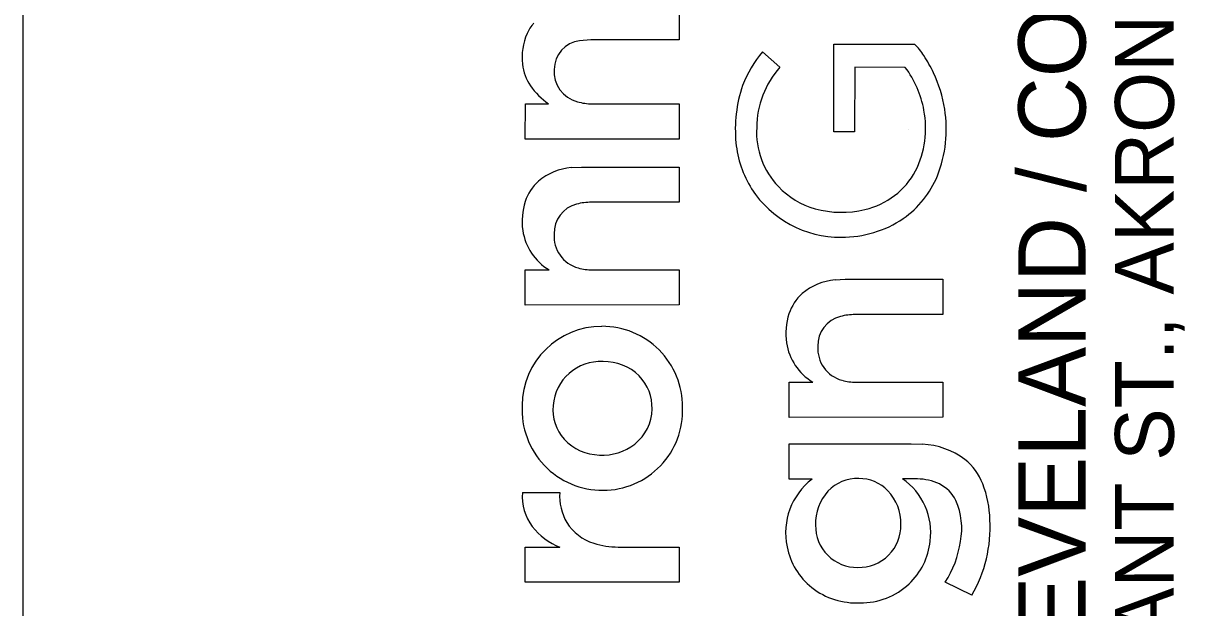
# Model space of a CAD drawing. Extents: x -1.9 to 34, y -1.1 to 22.
# Drawn here: x 32 to 32.984, y 3.094 to 3.59 of the extents above; entities that cross this region are included whole.
import ezdxf

# ---------------------------------------------------------------- set-up
doc = ezdxf.new("R2010")
doc.units = 0
doc.layers.add('SH_Border', color=7, linetype='Continuous')
doc.layers.add('SH_Data', color=7, linetype='Continuous')

msp = doc.modelspace()

# ---------------------------------------------------------------- linework, layer by layer
at = {"layer": 'SH_Border'}
msp.add_line((32, 0.5), (32, 21.5), dxfattribs=at)
at = {"layer": 'SH_Data'}
for p, q in [((32.55571, 3.60548), (32.55571, 3.57568)), ((32.4809, 3.57567), (32.47143, 3.57474)), ((32.55571, 3.57568), (32.4809, 3.57567)), ((32.62636, 3.56548), (32.64114, 3.55241)), ((32.6868, 3.57185), (32.75516, 3.57192)), ((32.6868, 3.49778), (32.6868, 3.57185)), ((32.70448, 3.55241), (32.70432, 3.49775)), ((32.74737, 3.55227), (32.70448, 3.55241)), ((32.42542, 3.49152), (32.42545, 3.52138)), ((32.42545, 3.52138), (32.44515, 3.52138)), ((32.48206, 3.52138), (32.55571, 3.52136)), ((32.55571, 3.52136), (32.55571, 3.49156)), ((32.70432, 3.49775), (32.6868, 3.49778)), ((32.75, 3.5), (32.75, 3.5)), ((32.55571, 3.49156), (32.42542, 3.49152)), ((32.46439, 3.46736), (32.47289, 3.46783)), ((32.47289, 3.46783), (32.55571, 3.46783)), ((32.55571, 3.46783), (32.55571, 3.43804)), ((32.55571, 3.43804), (32.4814, 3.43796)), ((32.42542, 3.38066), (32.44552, 3.38071)), ((32.42542, 3.35086), (32.42542, 3.38066)), ((32.48222, 3.38071), (32.55569, 3.38071)), ((32.55569, 3.38071), (32.55571, 3.35096)), ((32.68784, 3.3722), (32.69634, 3.37266)), ((32.69634, 3.37266), (32.77916, 3.37266)), ((32.77916, 3.37266), (32.77917, 3.34287)), ((32.55571, 3.35096), (32.42542, 3.35086)), ((32.77917, 3.34287), (32.70485, 3.3428)), ((32.64888, 3.2855), (32.66897, 3.28555)), ((32.64888, 3.25569), (32.64888, 3.2855)), ((32.70568, 3.28555), (32.77915, 3.28555)), ((32.77915, 3.28555), (32.77917, 3.25579)), ((32.77917, 3.25579), (32.64888, 3.25569)), ((32.6489, 3.20336), (32.64889, 3.23322)), ((32.64889, 3.23322), (32.75236, 3.23322)), ((32.75236, 3.23322), (32.76191, 3.23285)), ((32.66836, 3.20336), (32.6489, 3.20336)), ((32.75763, 3.20356), (32.74487, 3.20361)), ((32.42299, 3.19193), (32.45454, 3.19193)), ((32.42542, 3.14577), (32.45473, 3.14579)), ((32.42542, 3.11593), (32.42542, 3.14577)), ((32.50413, 3.14581), (32.55571, 3.14573)), ((32.55571, 3.14573), (32.55565, 3.11593)), ((32.55565, 3.11593), (32.42542, 3.11593)), ((32.8036, 3.10491), (32.7812, 3.11598))]:
    msp.add_line(p, q, dxfattribs=at)
for points in [[(32.48218, 3.60553), (32.55571, 3.60548), (32.55571, 3.57568), (32.4809, 3.57567), (32.47143, 3.57474)], [(32.62636, 3.56548), (32.64114, 3.55241)], [(32.74737, 3.55227), (32.70448, 3.55241), (32.70432, 3.49775), (32.6868, 3.49778), (32.6868, 3.57185), (32.75516, 3.57192)], [(32.42542, 3.49152), (32.42545, 3.52138), (32.44515, 3.52138)], [(32.48206, 3.52138), (32.55571, 3.52136), (32.55571, 3.49156), (32.42542, 3.49152)], [(32.46439, 3.46736), (32.47289, 3.46783), (32.55571, 3.46783), (32.55571, 3.43804), (32.4814, 3.43796)], [(32.42542, 3.35086), (32.42542, 3.38066), (32.44552, 3.38071)], [(32.48222, 3.38071), (32.55569, 3.38071), (32.55571, 3.35096), (32.42542, 3.35086)], [(32.68784, 3.3722), (32.69634, 3.37266), (32.77916, 3.37266), (32.77917, 3.34287), (32.70485, 3.3428)], [(32.64888, 3.25569), (32.64888, 3.2855), (32.66897, 3.28555)], [(32.70568, 3.28555), (32.77915, 3.28555), (32.77917, 3.25579), (32.64888, 3.25569)], [(32.66836, 3.20336), (32.6489, 3.20336), (32.64889, 3.23322), (32.75236, 3.23322), (32.76191, 3.23285)], [(32.75763, 3.20356), (32.74487, 3.20361)], [(32.42299, 3.19193), (32.45454, 3.19193)], [(32.50413, 3.14581), (32.55571, 3.14573), (32.55565, 3.11593), (32.42542, 3.11593)], [(32.42542, 3.11593), (32.42542, 3.14577), (32.45473, 3.14579)], [(32.8036, 3.10491), (32.7812, 3.11598)]]:
    msp.add_lwpolyline(points, dxfattribs=at)
for centre, radius, start, end in [((32.46194, 3.56452), 0.03875, 139.52447, 154.84698), ((32.46194, 3.56452), 0.03875, 139.52447, 154.84698), ((32.47144, 3.5612), 0.04877, 156.06382, 187.3493), ((32.47144, 3.5612), 0.04877, 156.06382, 187.3493), ((32.47421, 3.55056), 0.02434, 96.5532, 179.94902), ((32.47421, 3.55056), 0.02434, 96.5532, 179.94902), ((32.70163, 3.50187), 0.09855, 139.79476, 159.13696), ((32.70163, 3.50187), 0.09855, 139.79476, 159.13696), ((32.72498, 3.53937), 0.04438, 30.98913, 47.16099), ((32.72498, 3.53937), 0.04438, 30.98913, 47.16099), ((32.46461, 3.55974), 0.04181, 186.5579, 213.38846), ((32.46461, 3.55974), 0.04181, 186.5579, 213.38846), ((32.67091, 3.50018), 0.11106, 25.30315, 33.96179), ((32.67091, 3.50018), 0.11106, 25.30315, 33.96179), ((32.47608, 3.54863), 0.02628, 175.722, 255.78627), ((32.47608, 3.54863), 0.02628, 175.722, 255.78627), ((32.69899, 3.50079), 0.07753, 138.25804, 179.70064), ((32.69899, 3.50079), 0.07753, 138.25804, 179.70064), ((32.67889, 3.50099), 0.08556, 10.07509, 36.83189), ((32.67889, 3.50099), 0.08556, 10.07509, 36.83189), ((32.6704, 3.49987), 0.11166, 8.80339, 25.33484), ((32.6704, 3.49987), 0.11166, 8.80339, 25.33484), ((32.47886, 3.57078), 0.0598, 214.70433, 235.68724), ((32.47886, 3.57078), 0.0598, 214.70433, 235.68724), ((32.7187, 3.49968), 0.11536, 161.14379, 185.62812), ((32.7187, 3.49968), 0.11536, 161.14379, 185.62812), ((32.48195, 3.56518), 0.0438, 253.66719, 270.14979), ((32.48195, 3.56518), 0.0438, 253.66719, 270.14979), ((32.68425, 3.50057), 0.08036, 333.46689, 11.03668), ((32.68425, 3.50057), 0.08036, 333.46689, 11.03668), ((32.67564, 3.49977), 0.10649, 338.28866, 9.28548), ((32.67564, 3.49977), 0.10649, 338.28866, 9.28548), ((32.68811, 3.49732), 0.06676, 176.66577, 223.6912), ((32.68811, 3.49732), 0.06676, 176.66577, 223.6912), ((32.69336, 3.49699), 0.08987, 185.50773, 212.01294), ((32.69336, 3.49699), 0.08987, 185.50773, 212.01294), ((32.46871, 3.41767), 0.04988, 94.97056, 130.22484), ((32.46871, 3.41767), 0.04988, 94.97056, 130.22484), ((32.69868, 3.49547), 0.0652, 282.88151, 331.81475), ((32.69868, 3.49547), 0.0652, 282.88151, 331.81475), ((32.46348, 3.42602), 0.04016, 132.22383, 161.68229), ((32.46348, 3.42602), 0.04016, 132.22383, 161.68229), ((32.69835, 3.49168), 0.08241, 305.03061, 337.67573), ((32.69835, 3.49168), 0.08241, 305.03061, 337.67573), ((32.69211, 3.49748), 0.08908, 212.70222, 270.71399), ((32.69211, 3.49748), 0.08908, 212.70222, 270.71399), ((32.69045, 3.50011), 0.07039, 224.02147, 253.88), ((32.69045, 3.50011), 0.07039, 224.02147, 253.88), ((32.47872, 3.42158), 0.05602, 162.27398, 187.79173), ((32.47872, 3.42158), 0.05602, 162.27398, 187.79173), ((32.47482, 3.41206), 0.02498, 103.68683, 182.21395), ((32.47482, 3.41206), 0.02498, 103.68683, 182.21395), ((32.48108, 3.39196), 0.04601, 89.60515, 105.33026), ((32.48108, 3.39196), 0.04601, 89.60515, 105.33026), ((32.69318, 3.51254), 0.08309, 254.45353, 283.9512), ((32.69318, 3.51254), 0.08309, 254.45353, 283.9512), ((32.69429, 3.49979), 0.09138, 269.3273, 304.19632), ((32.69429, 3.49979), 0.09138, 269.3273, 304.19632), ((32.47027, 3.42141), 0.04763, 188.96462, 238.69865), ((32.47027, 3.42141), 0.04763, 188.96462, 238.69865), ((32.47735, 3.40897), 0.02757, 175.58441, 255.13816), ((32.47735, 3.40897), 0.02757, 175.58441, 255.13816), ((32.48183, 3.42286), 0.04215, 254.08913, 270.52838), ((32.48183, 3.42286), 0.04215, 254.08913, 270.52838), ((32.69216, 3.32251), 0.04988, 94.97056, 130.22484), ((32.69216, 3.32251), 0.04988, 94.97056, 130.22484), ((32.68694, 3.33085), 0.04016, 132.22383, 161.68229), ((32.68694, 3.33085), 0.04016, 132.22383, 161.68229), ((32.70217, 3.32642), 0.05602, 162.27398, 187.79173), ((32.70217, 3.32642), 0.05602, 162.27398, 187.79173), ((32.69828, 3.31689), 0.02498, 103.68683, 182.21395), ((32.69828, 3.31689), 0.02498, 103.68683, 182.21395), ((32.70453, 3.29679), 0.04601, 89.60515, 105.33026), ((32.70453, 3.29679), 0.04601, 89.60515, 105.33026), ((32.49014, 3.26543), 0.0674, 89.84756, 179.64047), ((32.49014, 3.26543), 0.0674, 89.84756, 179.64047), ((32.49057, 3.26474), 0.0681, 359.54009, 90.21138), ((32.49057, 3.26474), 0.0681, 359.54009, 90.21138), ((32.69372, 3.32624), 0.04763, 188.96462, 238.69865), ((32.69372, 3.32624), 0.04763, 188.96462, 238.69865), ((32.7008, 3.31381), 0.02757, 175.58441, 255.13816), ((32.7008, 3.31381), 0.02757, 175.58441, 255.13816), ((32.48923, 3.26263), 0.0404, 87.04809, 175.57259), ((32.48923, 3.26263), 0.0404, 87.04809, 175.57259), ((32.49204, 3.25999), 0.04299, 45.84264, 90.98008), ((32.49204, 3.25999), 0.04299, 45.84264, 90.98008), ((32.49458, 3.26421), 0.03821, 357.88569, 44.15902), ((32.49458, 3.26421), 0.03821, 357.88569, 44.15902), ((32.70529, 3.32769), 0.04215, 254.08913, 270.52838), ((32.70529, 3.32769), 0.04215, 254.08913, 270.52838), ((32.49083, 3.26209), 0.06819, 176.8344, 270.40384), ((32.49083, 3.26209), 0.06819, 176.8344, 270.40384), ((32.48729, 3.2625), 0.03848, 175.15378, 221.14706), ((32.48729, 3.2625), 0.03848, 175.15378, 221.14706), ((32.49123, 3.26139), 0.06749, 270.06243, 2.37759), ((32.49123, 3.26139), 0.06749, 270.06243, 2.37759), ((32.49446, 3.26318), 0.0383, 308.28936, 359.43468), ((32.49446, 3.26318), 0.0383, 308.28936, 359.43468), ((32.48919, 3.26607), 0.04228, 223.09994, 268.80895), ((32.48919, 3.26607), 0.04228, 223.09994, 268.80895), ((32.49096, 3.2679), 0.04418, 266.56515, 308.06078), ((32.49096, 3.2679), 0.04418, 266.56515, 308.06078), ((32.75907, 3.16789), 0.06503, 53.40344, 87.49062), ((32.75907, 3.16789), 0.06503, 53.40344, 87.49062), ((32.76517, 3.18039), 0.05141, 21.60748, 50.5577), ((32.76517, 3.18039), 0.05141, 21.60748, 50.5577), ((32.70292, 3.15813), 0.05692, 127.37482, 192.22468), ((32.70292, 3.15813), 0.05692, 127.37482, 192.22468), ((32.70693, 3.16927), 0.0346, 88.47302, 136.42562), ((32.70693, 3.16927), 0.0346, 88.47302, 136.42562), ((32.70814, 3.16963), 0.03424, 44.27195, 90.47623), ((32.70814, 3.16963), 0.03424, 44.27195, 90.47623), ((32.71421, 3.15829), 0.05472, 352.1125, 55.92295), ((32.71421, 3.15829), 0.05472, 352.1125, 55.92295), ((32.75666, 3.15725), 0.04633, 65.01687, 88.8011), ((32.75666, 3.15725), 0.04633, 65.01687, 88.8011), ((32.7626, 3.17155), 0.03085, 26.26808, 63.80301), ((32.7626, 3.17155), 0.03085, 26.26808, 63.80301), ((32.73069, 3.16714), 0.08835, 1.15143, 21.3627), ((32.73069, 3.16714), 0.08835, 1.15143, 21.3627), ((32.46616, 3.18882), 0.04329, 175.87313, 216.34747), ((32.46616, 3.18882), 0.04329, 175.87313, 216.34747), ((32.50087, 3.18948), 0.04639, 176.9688, 209.60636), ((32.50087, 3.18948), 0.04639, 176.9688, 209.60636), ((32.71141, 3.16602), 0.0401, 137.46739, 182.33237), ((32.71141, 3.16602), 0.0401, 137.46739, 182.33237), ((32.70368, 3.166), 0.03996, 358.57141, 43.53765), ((32.70368, 3.166), 0.03996, 358.57141, 43.53765), ((32.73565, 3.16154), 0.05953, 349.30734, 23.43071), ((32.73565, 3.16154), 0.05953, 349.30734, 23.43071), ((32.47466, 3.19716), 0.05511, 218.09809, 248.7907), ((32.47466, 3.19716), 0.05511, 218.09809, 248.7907), ((32.49514, 3.18814), 0.04079, 211.94466, 253.2028), ((32.49514, 3.18814), 0.04079, 211.94466, 253.2028), ((32.70645, 3.1637), 0.03511, 178.88208, 271.08374), ((32.70645, 3.1637), 0.03511, 178.88208, 271.08374), ((32.70818, 3.16404), 0.03546, 268.27882, 1.55016), ((32.70818, 3.16404), 0.03546, 268.27882, 1.55016), ((32.70538, 3.16244), 0.11383, 329.6388, 3.25998), ((32.70538, 3.16244), 0.11383, 329.6388, 3.25998), ((32.70988, 3.15708), 0.05887, 313.74196, 353.8554), ((32.70988, 3.15708), 0.05887, 313.74196, 353.8554), ((32.70738, 3.16334), 0.08771, 327.31495, 351.57478), ((32.70738, 3.16334), 0.08771, 327.31495, 351.57478), ((32.50465, 3.2165), 0.07069, 252.46555, 269.57296), ((32.50465, 3.2165), 0.07069, 252.46555, 269.57296), ((32.70463, 3.15696), 0.05837, 190.75182, 231.28919), ((32.70463, 3.15696), 0.05837, 190.75182, 231.28919), ((32.70632, 3.16112), 0.06269, 232.46061, 272.59022), ((32.70632, 3.16112), 0.06269, 232.46061, 272.59022), ((32.70954, 3.15901), 0.06051, 269.6361, 312.70877), ((32.70954, 3.15901), 0.06051, 269.6361, 312.70877)]:
    msp.add_arc(centre, radius, start, end, dxfattribs=at)

# ---------------------------------------------------------------- texts
for s, height, p in [('450 GRANT ST., AKRON, OH  44311', 0.0498462, (32.97489, 2.83738)), ('AKRON / CLEVELAND / COLUMBUS', 0.056969, (32.90012, 2.638))]:
    msp.add_text(s, height=height, rotation=90, dxfattribs=at).set_placement(p)

doc.saveas('drawing.dxf')
